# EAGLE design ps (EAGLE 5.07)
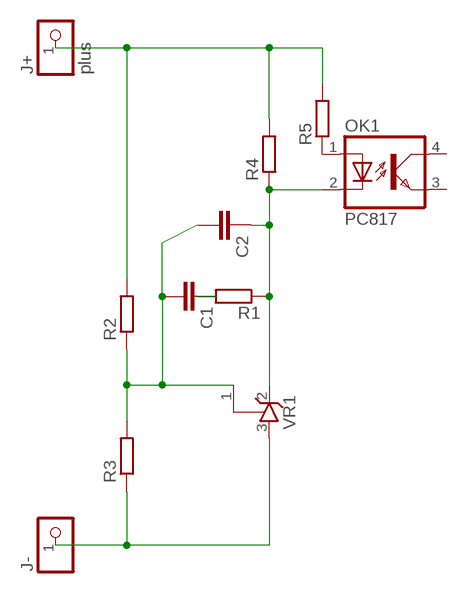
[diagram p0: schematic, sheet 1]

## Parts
C1  C-EUC1206  [C1206]
C2  C-EUC0805  [C0805]
J+  plus  PINHD-1X11X0.4  [1X01]
J-  PINHD-1X11X0.4  [1X01]
OK1  PC817  [DIL04]
R1  R-EU_R0805  [R0805]
R2  R-EU_R0805  [R0805]
R3  R-EU_R0805  [R0805]
R4  R-EU_R0805  [R0805]
R5  R-EU_R0805  [R0805]
VR1  TL431CLPSOT23  [SOT23]

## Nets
N$1: J-.1 R3.1 VR1.3(A)
N$2: C1.2 C2.2 R2.1 R3.2 VR1.1(R)
N$3: C1.1 R1.2
N$5: J+.1 R2.2 R4.2 R5.2
N$6: C2.1 OK1.2(C) R1.1 R4.1 VR1.2(C)
N$7: OK1.1(A) R5.1
Unconnected: OK1.3(EMIT) OK1.4(COL)

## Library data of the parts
C1 C2 = rcl:C-EU: CAPACITOR, European symbol
J+ J- = pinhead:PINHD-1X1: PIN HEADER
OK1 = optocoupler:PC817: SHARP OPTO COUPLER
R1-R5 = rcl:R-EU_: RESISTOR, European symbol
VR1 = v-reg:TL431CLP: VOLTAGE REGULATOR

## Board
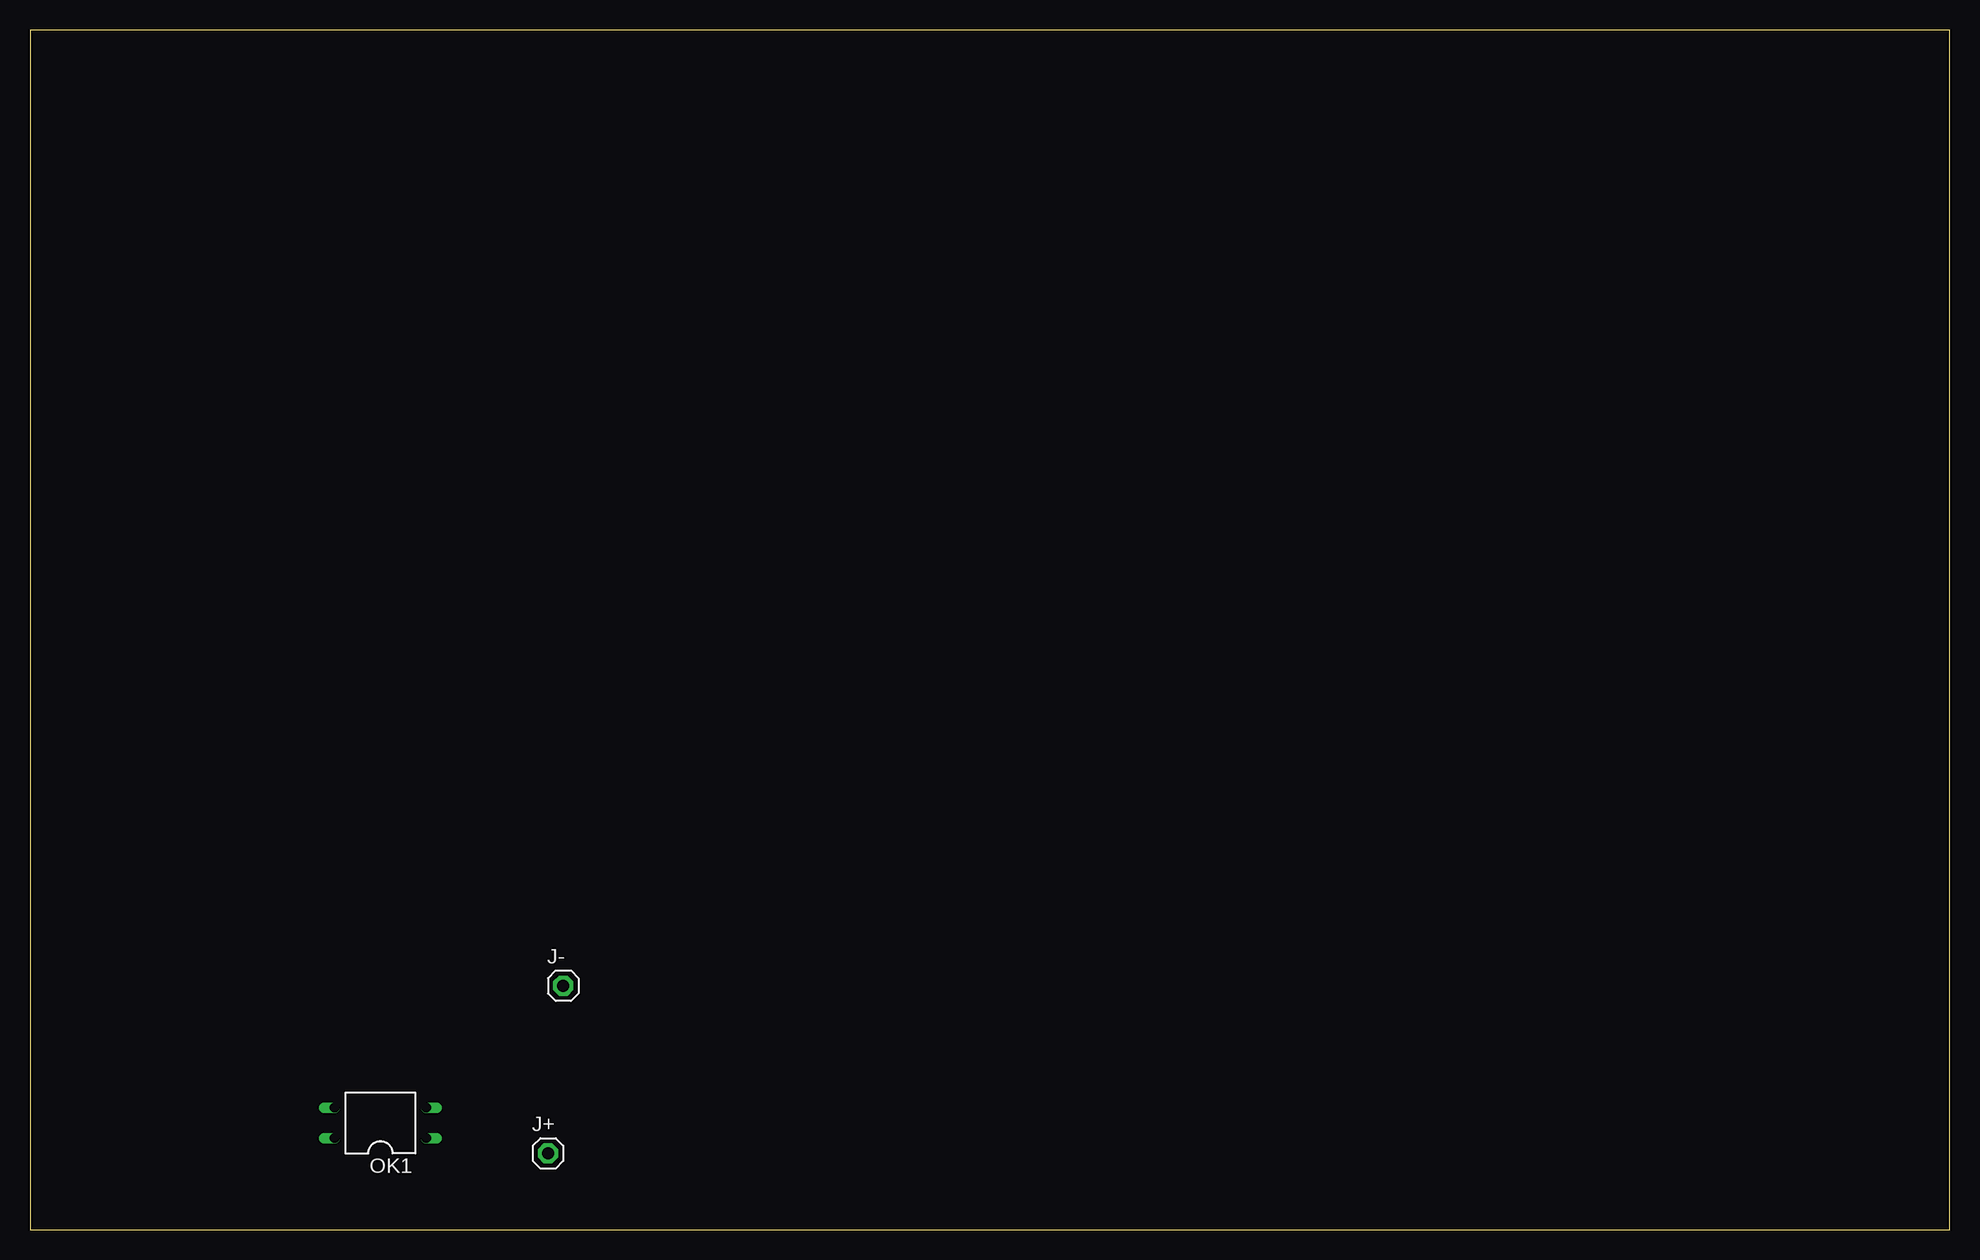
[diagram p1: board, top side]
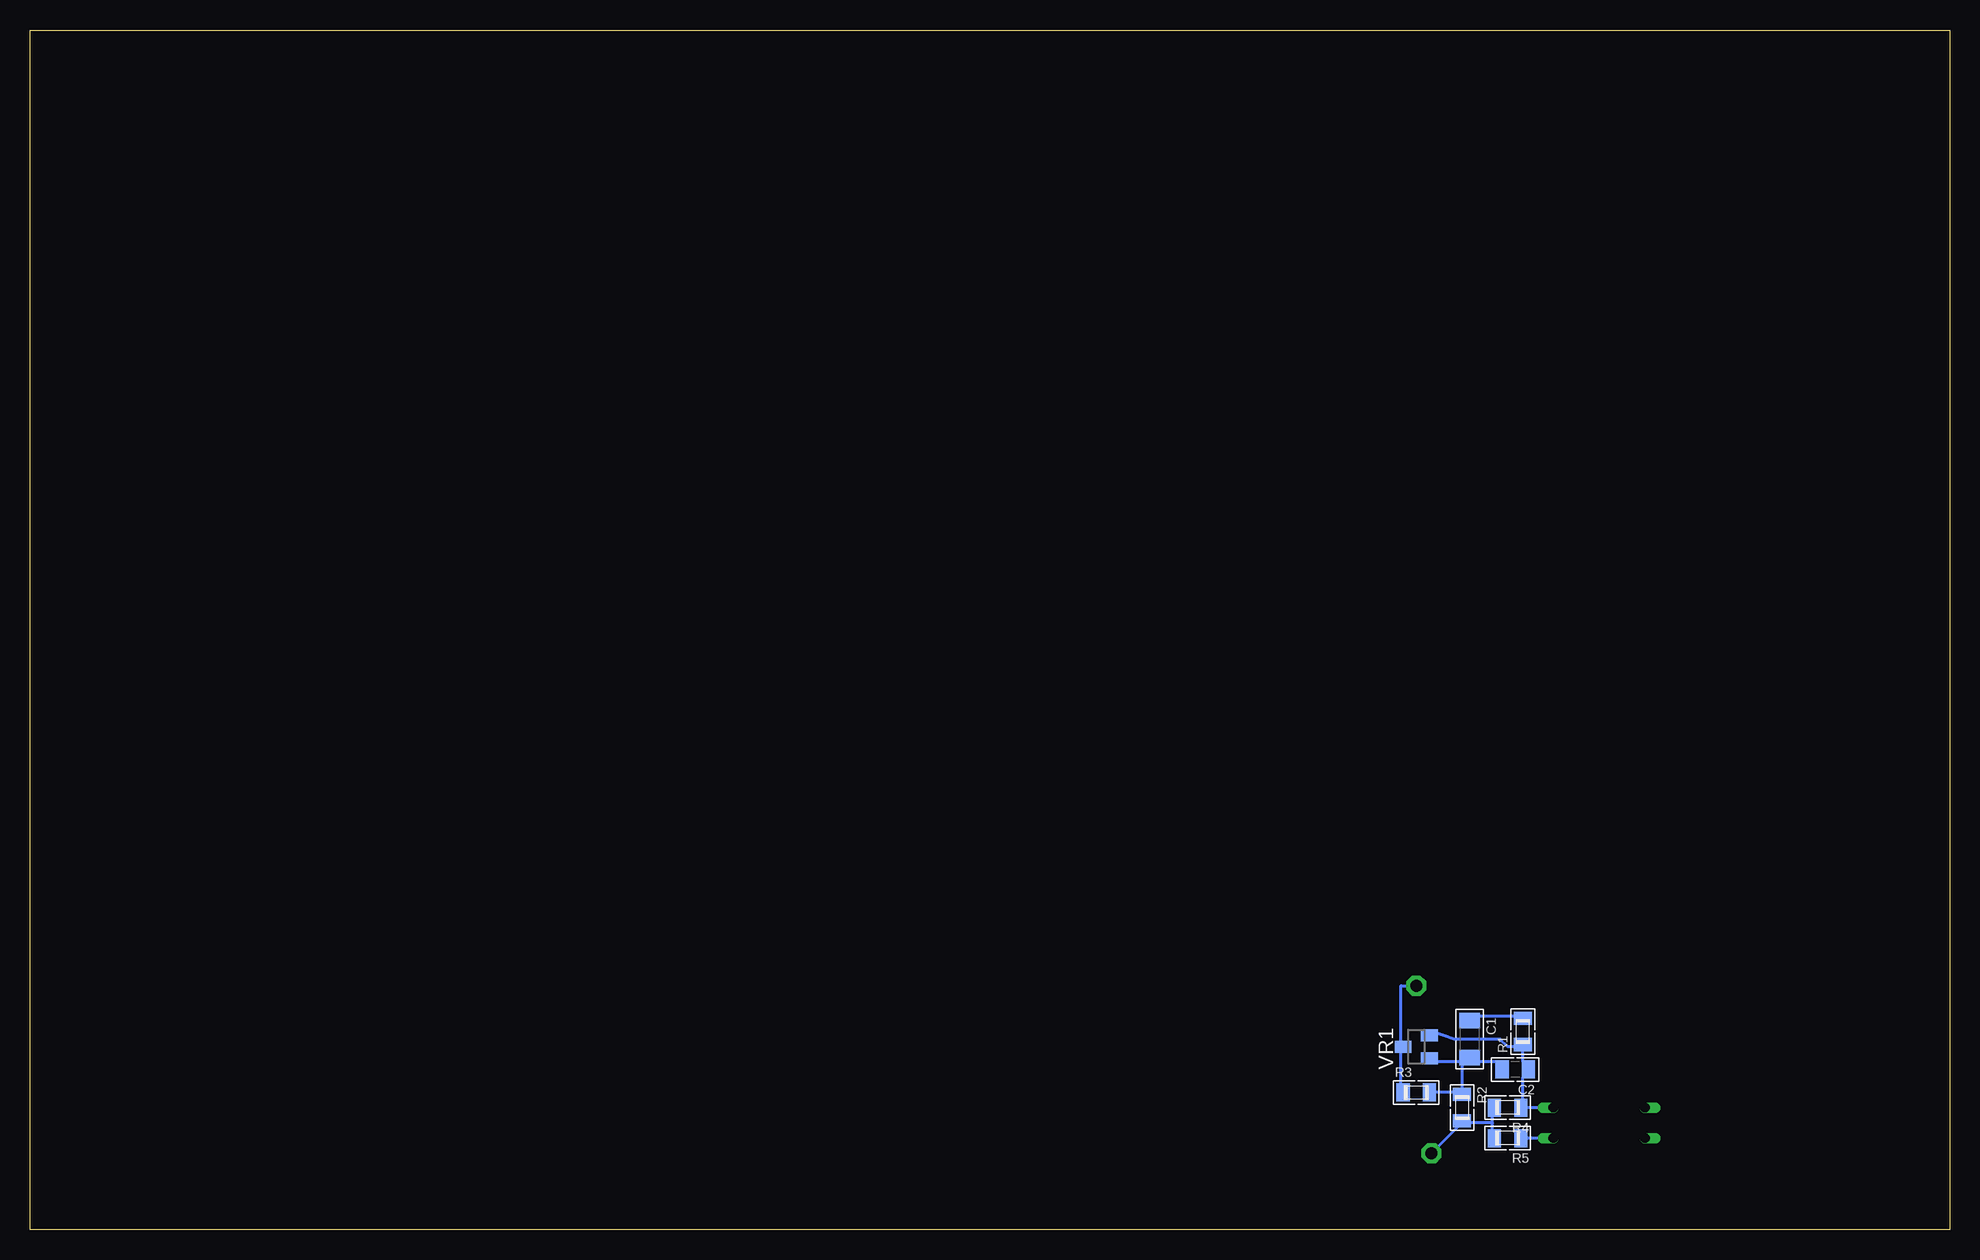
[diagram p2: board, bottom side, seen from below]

Size 160 x 100 mm. Coordinates in mm from the lower left corner, seen from the top.
Outline: 0,0 160,0 160,100 0,100 0,0
Copper layers (1*16): Top 0.035mm / dielectric 1.5mm / Bottom 0.035mm
Design rules "default": minimum track width 10mil, minimum drill 20mil, track to track 8mil, track to pad 8mil, pad to pad 8mil, via to via 8mil, smd to smd 8mil, copper to edge 40mil, drill to drill 8mil, minimum pad ring 1mil, minimum via ring 8mil, stop-mask expansion 4mil, vias tented up to drill 0mil, thermal gap 10mil

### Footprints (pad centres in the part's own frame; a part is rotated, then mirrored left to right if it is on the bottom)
C1206 = smd 1.3 x 1.7: 1 -1.55,0; 2 1.55,0
C0805 = smd 1.1 x 1.5: 1 -1.1,0; 2 1.1,0
1X01 = drill 1 pad 1.676 octagon: 1 0,0
DIL04 = drill 0.813 offset: 1 -1.27,-3.81; 2 1.27,-3.81; 3 1.27,3.81; 4 -1.27,3.81
R0805 = smd 1.1 x 1.5: 1 -1.1,0; 2 1.1,0
SOT23 = smd 1 x 1.4: 1 -0.95,-1.1; 2 0.95,-1.1; 3 0,1.1

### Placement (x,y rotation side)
C1  40.01,15.88 270 bottom
C2  36.2,13.34 180 bottom
J+  43.18,6.35 0 top
J-  44.45,20.32 0 top
OK1  29.21,8.89 90 top
R1  35.56,16.51 90 bottom
R2  40.64,10.16 270 bottom
R3  44.45,11.43 0 bottom
R4  36.83,10.16 180 bottom
R5  36.83,7.62 180 bottom
VR1  44.45,15.24 90 bottom

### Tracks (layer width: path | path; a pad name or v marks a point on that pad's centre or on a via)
N$1
  Bottom 0.254: 45.72,15.24 45.72,11.43 R3.1 | 45.72,15.24 45.72,20.32 J-.1 | 45.72,15.24 VR1.3
N$2
  Bottom 0.254: 40.64,13.97 43.18,13.97 VR1.1 | C2.2 36.83,13.97 39.37,13.97 C1.2 40.64,13.97 | 40.64,13.97 40.64,11.43 | 40.64,11.43 R3.2 | 40.64,11.43 R2.1
N$3
  Bottom 0.254: R1.2 35.56,17.78 39.37,17.78 C1.1
N$5
  Bottom 0.254: 38.1,8.89 38.1,10.16 R4.2 | 38.1,8.89 38.1,7.62 R5.2 | 38.1,8.89 40.64,8.89 | 40.64,8.89 J+.1 | 40.64,8.89 R2.2
N$6
  Bottom 0.254: OK1.2 35.56,10.16 | 35.56,15.24 36.83,15.24 37.47,15.88 41.27,15.88 43.18,16.51 VR1.2 | 35.56,15.24 35.56,13.97 C2.1 35.56,12.7 35.56,10.16 | 35.56,15.24 R1.1 | 35.56,10.16 R4.1
N$7
  Bottom 0.254: OK1.1 R5.1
